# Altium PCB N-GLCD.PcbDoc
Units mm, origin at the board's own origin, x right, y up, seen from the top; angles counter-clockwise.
Board outline 33.02 x 15.24 mm, 2 copper layers (Top Layer, Bottom Layer), stack 1.571 mm thick; 8 components, 17 nets, 66 pads, 11 vias.
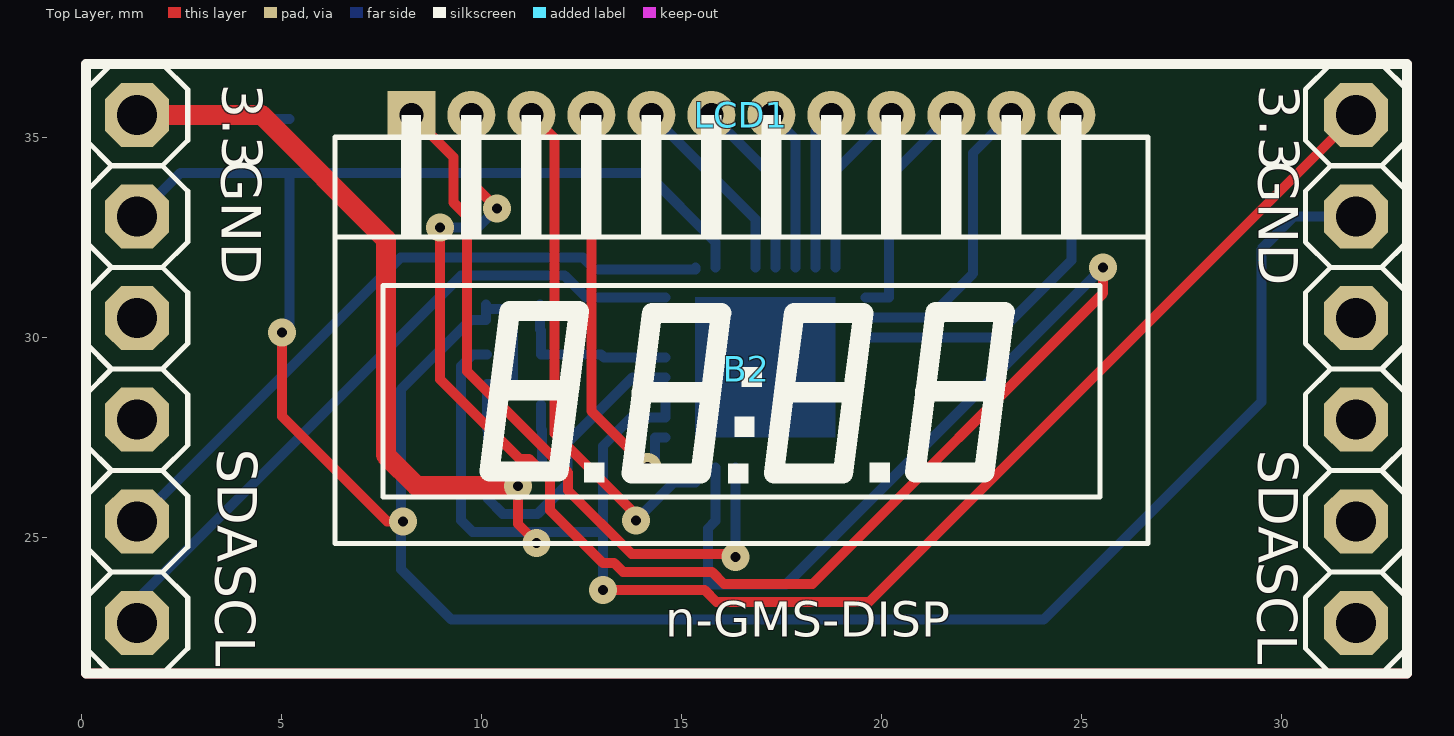
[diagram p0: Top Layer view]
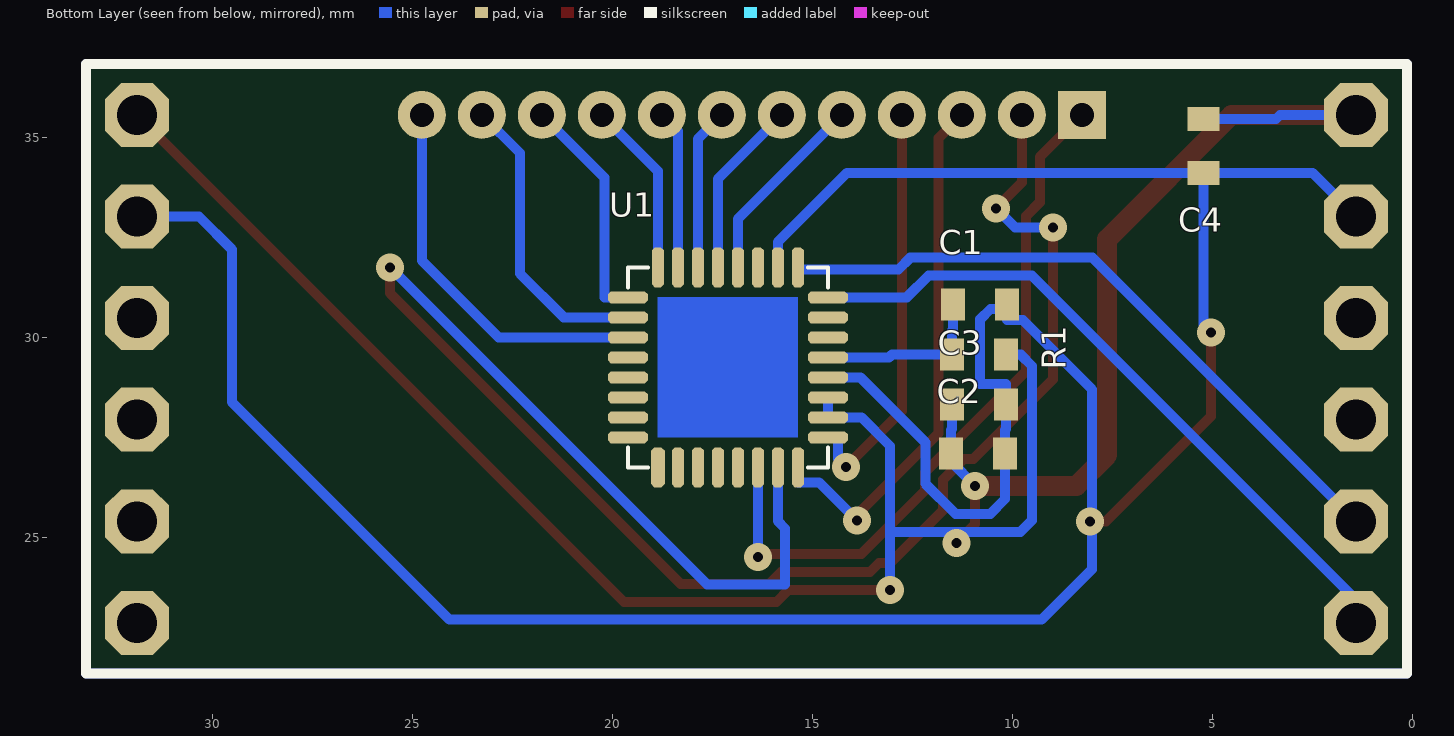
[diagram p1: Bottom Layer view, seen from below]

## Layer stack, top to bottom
Top Solder: solder mask 0.0102, Solder Resist, Dk 3.5
Top Layer: signal copper 0.0356
Dielectric 1: dielectric 1.5, FR-4, Dk 4.8
Bottom Layer: signal copper 0.0356
Bottom Solder: solder mask 0.0102, Solder Resist, Dk 3.5

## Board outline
0.127,21.59 33.147,21.59 33.147,36.83 0.127,36.83

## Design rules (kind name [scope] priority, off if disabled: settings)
Clearance [All] p1: gap=0.2
PolygonConnect [All] p1: connectstyle=Relief reliefconductorwidth=0.254 reliefentries=4 polygonreliefangle="90 Angle" airgapwidth=0.254
RoomDefinition N-GLCD [InComponentClass('N-GLCD')] p1: confinementstyle=ConfineIn formatcopy=TRUE lockcomponents=FALSE outline 34.417,44.196 -2.159,44.196 -2.159,-1.397 34.417,-1.397
RoutingVias [All] p1: holewidth=0.25 width=0.7 viastyle="Through Hole" minholewidth=0.25 minwidth=0.7 maxholewidth=0.25 maxwidth=0.7
SolderMaskExpansion [All] p1: expansion=0.102
Width [All] p1: maxlimit=1.27 minlimit=0.25 preferedwidth=0.25
30 further rules are at their usual default settings.

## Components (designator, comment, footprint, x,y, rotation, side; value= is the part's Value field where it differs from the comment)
B2 "N-GMS-DISP" N-GMS-DISP 1.397,35.56 r270 top locked
C1 "100nF" 0603_cap 10.81,30.815 r180 bottom
C2 "100nF" 0603_cap 10.835,27.09 r0 bottom
C3 "100nF" 0603_cap 10.835,28.315 r180 bottom
C4 "100nF" 0603_cap 5.207,34.798 r270 bottom
LCD1 "S401M16KR" LCD-S401M16KR 8.255,35.56 r0 top locked
R1 "10K" 0603_res 10.81,29.565 r0 bottom
U1 "PCA8561AHN" QFN32-HVQFN32_0.5mm_LONG 14.605,31.75 r0 bottom

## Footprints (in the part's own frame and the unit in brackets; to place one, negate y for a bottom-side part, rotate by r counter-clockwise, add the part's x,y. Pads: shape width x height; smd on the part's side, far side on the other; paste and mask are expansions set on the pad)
0603_cap [mm]
  rect 0.6x0.8 smd: 1(-0.66,0) 2(0.686,0)
  body extent -0.8,-0.4 0.8,0.4, height 0.3
0603_res [mm]
  rect 0.6x0.8 smd: 1(-0.66,0) 2(0.686,0)
  body extent -0.8,-0.4 0.8,0.4, height 0.3
LCD-S401M16KR [mm]
  rect 1.2x1.2 hole 0.6: 1(0,0)
  round 1.2 hole 0.6: 2(1.5,0) 3(3,0) 4(4.5,0) 5(6,0) 6(7.5,0) 7(9,0) 8(10.5,0) 9(12,0) 10(13.5,0) 11(15,0) 12(16.5,0)
  silkscreen extent -1.91,-10.72 18.41,0
N-GMS-DISP [mil]
  oct 63x63 hole 39.37: 1(0,0) 2(100,0) 3(200,0) 4(300,0) 5(400,0) 6(500,0) 7(500,1200) 8(400,1200) 9(300,1200) 10(200,1200) 11(100,1200) 12(0,1200)
  silkscreen extent -50,-50 550,1250, body extent -48,-48 552,1250, height 331
QFN32-HVQFN32_0.5mm_LONG [mm]
  oct 1x0.3 smd: 1(0,4.25) 2(0,3.75) 3(0,3.25) 4(0,2.75) 5(0,2.25) 6(0,1.75) 7(0,1.25) 8(0,0.75) 17(5,0.75) 18(5,1.25) 19(5,1.75) 20(5,2.25) 21(5,2.75) 22(5,3.25) 23(5,3.75) 24(5,4.25)
  oct 0.3x1 smd: 9(0.75,0) 10(1.25,0) 11(1.75,0) 12(2.25,0) 13(2.75,0) 14(3.25,0) 15(3.75,0) 16(4.25,0) 26(3.75,5) 27(3.25,5) 28(2.75,5) 29(2.25,5) 30(1.75,5) 31(1.25,5) 32(0.75,5)
  oct 0.35x1 smd: 25(4.25,5)
  Top Layer region: 0.75,4.25 4.25,4.25 4.25,0.75 0.75,0.75
  silkscreen extent 0,0 5,5, body extent 0,0 5,5, height 0.97

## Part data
C1 C2 C3 C4: library part C, "CAPACITOR"
LCD1: library part LCD-S401M16KR
R1: library part R, "RESISTOR"

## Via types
v1: diameter 0.7, hole 0.25, Top Layer to Bottom Layer, tented both sides, 11 vias

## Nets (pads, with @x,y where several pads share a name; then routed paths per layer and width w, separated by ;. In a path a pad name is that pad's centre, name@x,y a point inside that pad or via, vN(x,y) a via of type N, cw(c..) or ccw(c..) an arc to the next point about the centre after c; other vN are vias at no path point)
3.3V: B2.1 B2.12 C2.2 C3.1 C4.1 R1.1 U1.2 U1.3 | length 62.9
  Top Layer w0.25: v1(10.922,26.289) 10.922,25.331 v1(11.39,24.863) ; v1(13.048,23.681) 15.592,23.681 15.889,23.383 19.7,23.383 B2.12
  Top Layer w0.5: B2.1 4.515,35.56 7.62,32.455 7.62,27.055 8.386,26.289 v1(10.922,26.289)
  Bottom Layer w0.25: B2.1 3.302,35.56 3.404,35.458 C4.1 ; R1.1 9.779,29.566 9.5,29.286 9.5,25.425 9.786,25.139 11.115,25.139 ; v1(10.922,26.289) 11.521,26.888 C2.2 11.521,27.686 11.495,27.711 C3.1 ; v1(11.39,24.863) 11.115,25.139 ; v1(13.048,23.681) 13.048,25.139 ; U1.3 U1.2 13.764,28 13.048,27.283 13.048,25.139 ; 11.115,25.139 13.048,25.139
COM0: LCD1.1 U1.30 | length 18.1
  Top Layer w0.25: LCD1.1 9.305,34.51 9.305,33.374 9.65,33.03 9.65,29.152 12.175,26.627 12.175,26.172 13.767,24.581 16.283,24.581 v1(16.355,24.508)
  Bottom Layer w0.25: v1(16.355,24.508) U1.30
COM1: LCD1.2 U1.31 | length 47
  Top Layer w0.25: v1(8.975,32.75) 8.975,28.95 10.961,26.964 11.202,26.964 11.725,26.441 11.725,25.675 13.044,24.356 13.327,24.356 13.552,24.131 15.778,24.131 16.075,23.833 18.283,23.833 25.552,31.102 v1(25.552,31.75) ; LCD1.2 9.755,33.87 v1(10.4,33.225)
  Bottom Layer w0.25: v1(8.975,32.75) 9.925,32.75 v1(10.4,33.225) ; U1.31 15.855,25.405 15.672,25.222 15.672,23.825 17.628,23.825 v1(25.552,31.75)
COM2: LCD1.3 U1.32 | length 13.5
  Top Layer w0.25: LCD1.3 11.836,34.979 11.836,27.602 13.876,25.563 v1(13.876,25.426)
  Bottom Layer w0.25: v1(13.876,25.426) 14.824,26.375 15.355,26.375 U1.32
COM3: LCD1.4 U1.1 | length 10.5
  Top Layer w0.25: LCD1.4 12.755,28.158 v1(14.155,26.758)
  Bottom Layer w0.25: v1(14.155,26.758) 14.351,26.954 14.351,27.5 U1.1
GND: B2.2 B2.11 C1.2 C2.1 C3.2 C4.2 U1.4 U1.10 | length 77.7
  Top Layer w0.25: v1(5.025,30.125) 5.025,28.025 7.65,25.4 v1(8.05,25.4)
  Bottom Layer w0.25: B2.2 2.489,34.112 C4.2 ; v1(5.025,30.125) 5.207,30.307 C4.2 ; v1(8.05,25.4) v1@8,25.4 ; C1.2 C1.2@10.124,30.709 ; U1.4 13.792,29 12.167,27.374 12.167,26.34 11.416,25.589 10.541,25.589 10.175,25.955 C2.1 10.175,27.686 10.149,27.711 C3.2 10.149,28.829 10.795,28.829 10.795,30.455 10.541,30.709 C1.2@10.124,30.709 ; U1.10 15.855,32.385 14.128,34.112 C4.2 ; B2.11 30.325,33.02 29.505,32.2 29.505,28.38 24.065,22.94 9.26,22.94 8,24.2 v1@8,25.4 ; v1@8,25.4 8,28.701 9.728,30.429 10.124,30.429 C1.2@10.124,30.709
RESET: C1.1 R1.2 U1.5 | length 4.4
  Bottom Layer w0.25: C1.1 11.47,30.201 11.496,30.175 R1.2 13.005,29.565 13.07,29.5 U1.5
S0: LCD1.5 U1.12 | length 4.9
  Bottom Layer w0.25: LCD1.5 16.855,32.96 U1.12
S1: LCD1.6 U1.13 | length 4.5
  Bottom Layer w0.25: LCD1.6 17.355,33.96 U1.13
S2: LCD1.7 U1.14 | length 4.1
  Bottom Layer w0.25: LCD1.7 17.855,34.96 U1.14
S3: LCD1.8 U1.15 | length 4
  Bottom Layer w0.25: U1.15 18.355,35.16 LCD1.8
S4: LCD1.9 U1.16 | length 4.4
  Bottom Layer w0.25: U1.16 18.855,34.16 LCD1.9
S5: LCD1.10 U1.17 | length 5.8
  Bottom Layer w0.25: U1.17 20.193,31 20.193,33.998 LCD1.10
S6: LCD1.11 U1.18 | length 7.5
  Bottom Layer w0.25: U1.18 21.209,30.5 22.301,31.592 22.301,34.606 LCD1.11
S7: LCD1.12 U1.19 | length 9.6
  Bottom Layer w0.25: U1.19 22.837,30 24.755,31.918 LCD1.12
SCL: B2.6 U1.8 | length 17.4
  Bottom Layer w0.25: B2.6 1.397,23.437 9.5,31.54 12.09,31.54 12.631,31 U1.8
SDA: B2.5 U1.9 | length 16.9
  Bottom Layer w0.25: B2.5 7.987,31.99 12.545,31.99 12.836,31.699 15.355,31.699 U1.9
pads on no net: B2.3 B2.4 B2.7 B2.8 B2.9 B2.10 U1.6 U1.7 U1.11 U1.20 U1.21 U1.22 U1.23 U1.24 U1.25 U1.26 U1.27 U1.28 U1.29
copper on no net: | length 193
  Top Layer w0.25: 0.127,21.59 0.127,36.83 33.147,36.83 33.147,21.59 0.127,21.59
  Bottom Layer w0.25: 0.127,21.59 0.127,36.83 33.147,36.83 33.147,21.59 0.127,21.59

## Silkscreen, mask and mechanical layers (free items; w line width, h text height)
Top Overlay:
  the board outline again, w0.25
Bottom Overlay:
  the board outline again, w0.25
Mechanical 3:
  the board outline again, w0.2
